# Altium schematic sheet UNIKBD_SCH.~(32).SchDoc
size A4
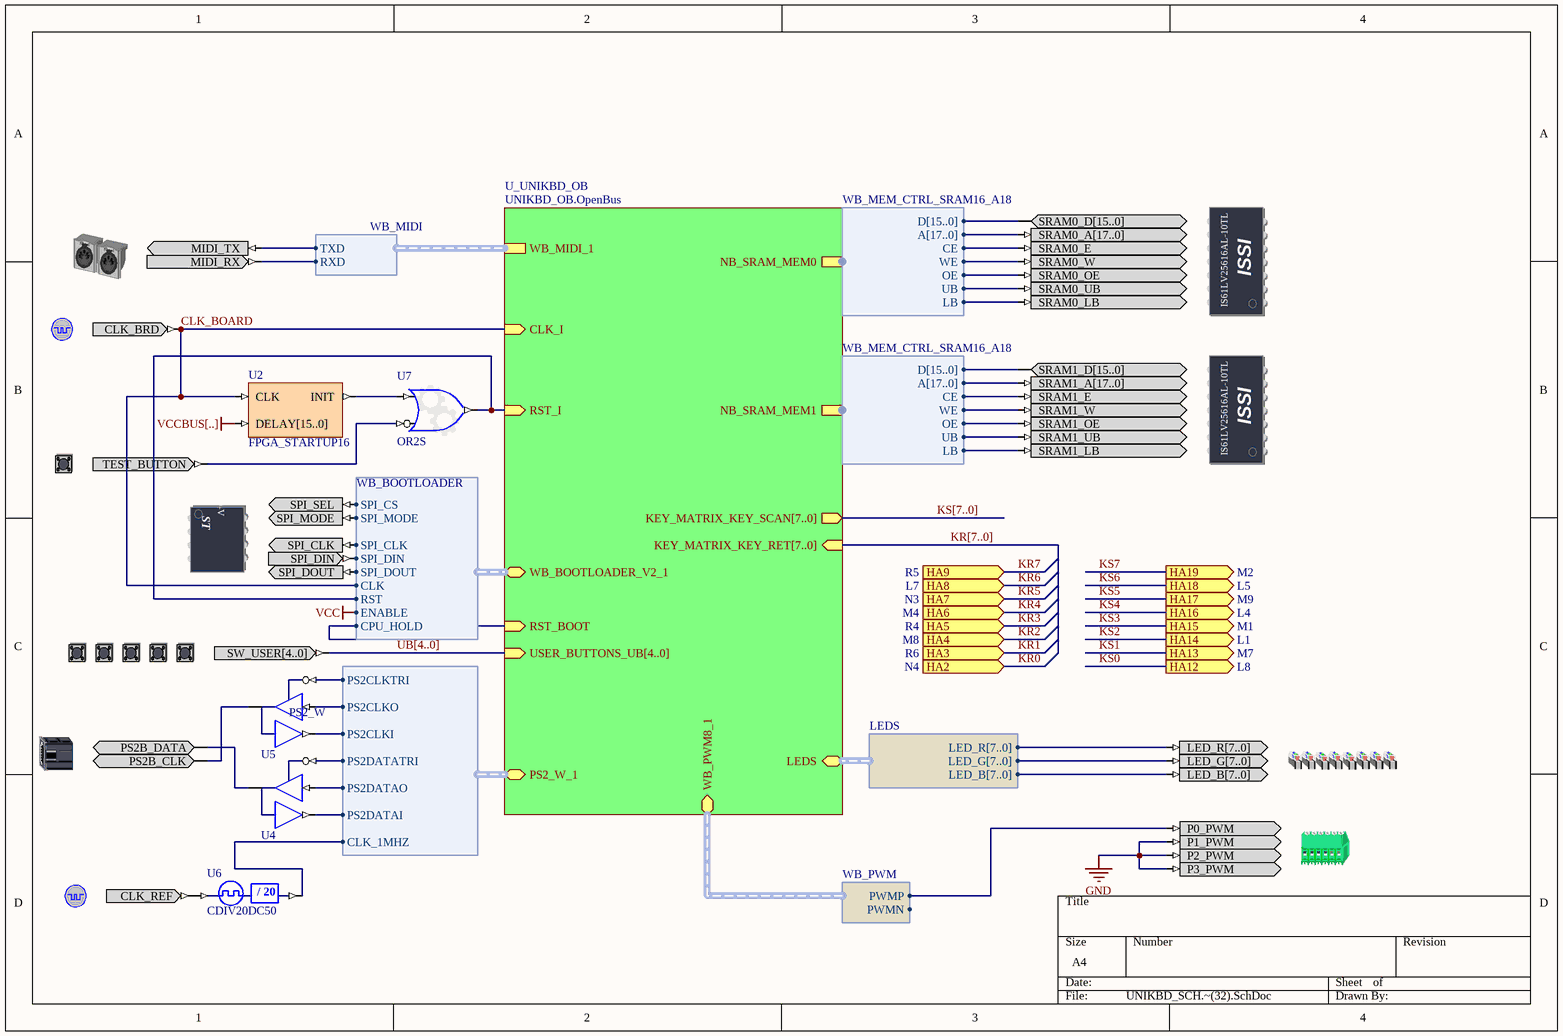
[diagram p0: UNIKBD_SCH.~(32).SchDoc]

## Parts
(Parts that share a designator on the sheet are numbered #1, #2 ... from top to bottom, then left to right.)
?#1  SRAM0  (value not drawn)
?#2  MIDI  (value not drawn)
?#3  CLOCK_BOARD  (value not drawn)
?#4  SRAM1  (value not drawn)
?#5  TEST_BUTTON  (value not drawn)
?#6  SERIALFMEMORY  (value not drawn)
?#7  USER_BUTTONS  (value not drawn)
?#8  LEDS_RGB  (value not drawn)
?#9  PS2B  (value not drawn)
?#10  PWM  (value not drawn)
?#11  CLOCK_REFERENCE  (value not drawn)
U2  FPGA_STARTUP16
U4  IOBUF  (value not drawn)
U5  IOBUF  (value not drawn)
U6  CDIV20DC50
U7  OR2S

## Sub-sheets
U_UNIKBD_OB = UNIKBD_OB.OpenBus: KEY_MATRIX_KEY_SCAN[7..0] (out), KEY_MATRIX_KEY_RET[7..0] (in), WB_MIDI_1 (harness WB_MIDI), NB_SRAM_MEM0 (harness WB_MEM_CTRL_SRAM16_A18), NB_SRAM_MEM1 (harness WB_MEM_CTRL_SRAM16_A18), RST_I (in), CLK_I (in), USER_BUTTONS_UB[4..0] (in), PS2_W_1 (harness PS2_W), LEDS (harness LEDS), WB_PWM8_1 (harness WB_PWM), WB_BOOTLOADER_V2_1 (harness WB_BOOTLOADER), RST_BOOT (in)

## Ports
HA2 (in, see N4), HA3 (in, see R6), HA4 (in, see M8), HA5 (in, see R4), HA6 (in, see M4), HA7 (in, see N3), HA8 (in, see L7), HA9 (in, see R5), HA12 (out, see L8), HA13 (out, see M7), HA14 (out, see L1), HA15 (out, see M1), HA16 (out, see L4), HA17 (out, see M9), HA18 (out, see L5), HA19 (out, see M2)

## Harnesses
WB_MEM_CTRL_SRAM16_A18: D[15..0], A[17..0], CE, WE, OE, UB, LB
WB_MIDI: RXD, TXD
LEDS: LED_R[7..0], LED_G[7..0], LED_B[7..0]
PS2_W: PS2CLKTRI, PS2CLKO, PS2CLKI, PS2DATATRI, PS2DATAO, PS2DATAI, CLK_1MHZ
WB_PWM: PWMN, PWMP
WB_BOOTLOADER: SPI_DOUT, SPI_DIN, SPI_CLK, SPI_MODE, SPI_CS, CLK, RST, ENABLE, CPU_HOLD

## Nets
GND: ?#10.P1_PWM ?#10.P2_PWM ?#10.P3_PWM
VCCBUS[..]: U2.DELAY[15..0]
CLK_BOARD: ?#3.CLK_BRD U2.CLK ; sheet U_UNIKBD_OB/CLK_I, sheet U_UNIKBD_OB/WB_BOOTLOADER_V2_1.CLK
Net?#1_SRAM0_E: ?#1.SRAM0_E ; sheet U_UNIKBD_OB/NB_SRAM_MEM0.CE
Net?#1_SRAM0_LB: ?#1.SRAM0_LB ; sheet U_UNIKBD_OB/NB_SRAM_MEM0.LB
Net?#1_SRAM0_OE: ?#1.SRAM0_OE ; sheet U_UNIKBD_OB/NB_SRAM_MEM0.OE
Net?#1_SRAM0_UB: ?#1.SRAM0_UB ; sheet U_UNIKBD_OB/NB_SRAM_MEM0.UB
Net?#1_SRAM0_W: ?#1.SRAM0_W ; sheet U_UNIKBD_OB/NB_SRAM_MEM0.WE
Net?#2_MIDI_RX: ?#2.MIDI_RX ; sheet U_UNIKBD_OB/WB_MIDI_1.RXD
Net?#2_MIDI_TX: ?#2.MIDI_TX ; sheet U_UNIKBD_OB/WB_MIDI_1.TXD
Net?#4_SRAM1_E: ?#4.SRAM1_E ; sheet U_UNIKBD_OB/NB_SRAM_MEM1.CE
Net?#4_SRAM1_LB: ?#4.SRAM1_LB ; sheet U_UNIKBD_OB/NB_SRAM_MEM1.LB
Net?#4_SRAM1_OE: ?#4.SRAM1_OE ; sheet U_UNIKBD_OB/NB_SRAM_MEM1.OE
Net?#4_SRAM1_UB: ?#4.SRAM1_UB ; sheet U_UNIKBD_OB/NB_SRAM_MEM1.UB
Net?#4_SRAM1_W: ?#4.SRAM1_W ; sheet U_UNIKBD_OB/NB_SRAM_MEM1.WE
Net?#5_TEST_BUTTON: ?#5.TEST_BUTTON U7.I1
Net?#6_SPI_CLK: ?#6.SPI_CLK ; sheet U_UNIKBD_OB/WB_BOOTLOADER_V2_1.SPI_CLK
Net?#6_SPI_DIN: ?#6.SPI_DIN ; sheet U_UNIKBD_OB/WB_BOOTLOADER_V2_1.SPI_DIN
Net?#6_SPI_DOUT: ?#6.SPI_DOUT ; sheet U_UNIKBD_OB/WB_BOOTLOADER_V2_1.SPI_DOUT
Net?#6_SPI_MODE: ?#6.SPI_MODE ; sheet U_UNIKBD_OB/WB_BOOTLOADER_V2_1.SPI_MODE
Net?#6_SPI_SEL: ?#6.SPI_SEL ; sheet U_UNIKBD_OB/WB_BOOTLOADER_V2_1.SPI_CS
Net?#9_PS2B_CLK: ?#9.PS2B_CLK U5.IO
Net?#9_PS2B_DATA: ?#9.PS2B_DATA U4.IO
Net?#10_P0_PWM: ?#10.P0_PWM ; sheet U_UNIKBD_OB/WB_PWM8_1.PWMP
Net?#11_CLK_REF: ?#11.CLK_REF U6.CLKIN
NetU2_INIT: U2.INIT U7.I0
NetU4_I: U4.I ; sheet U_UNIKBD_OB/PS2_W_1.PS2DATAO
NetU4_O: U4.O ; sheet U_UNIKBD_OB/PS2_W_1.PS2DATAI
NetU4_T: U4.T ; sheet U_UNIKBD_OB/PS2_W_1.PS2DATATRI
NetU5_I: U5.I ; sheet U_UNIKBD_OB/PS2_W_1.PS2CLKO
NetU5_O: U5.O ; sheet U_UNIKBD_OB/PS2_W_1.PS2CLKI
NetU5_T: U5.T ; sheet U_UNIKBD_OB/PS2_W_1.PS2CLKTRI
NetU6_CLKDV: U6.CLKDV ; sheet U_UNIKBD_OB/PS2_W_1.CLK_1MHZ
NetU7_O: U7.O ; sheet U_UNIKBD_OB/RST_I, sheet U_UNIKBD_OB/WB_BOOTLOADER_V2_1.RST
(unnamed): sheet U_UNIKBD_OB/RST_BOOT, sheet U_UNIKBD_OB/WB_BOOTLOADER_V2_1.CPU_HOLD

Not connected (* = marked no-connect by the designer): ?#1 SRAM0_A[17..0] SRAM0_D[15..0]; ?#4 SRAM1_A[17..0] SRAM1_D[15..0]; ?#7 SW_USER[4..0]; ?#8 LED_B[7..0] LED_G[7..0] LED_R[7..0]

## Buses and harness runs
bus KR[7..0] = sheet U_UNIKBD_OB/KEY_MATRIX_KEY_RET[7..0]
bus KS[7..0] = sheet U_UNIKBD_OB/KEY_MATRIX_KEY_SCAN[7..0]
bus UB[4..0] = sheet U_UNIKBD_OB/USER_BUTTONS_UB[4..0]

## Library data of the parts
?#1 = SRAM0: Free Static RAM - Daughterboard; PortComponent: True
?#2 = MIDI: MIDI Connector; PortComponent: True
?#3 = CLOCK_BOARD: Global System Clock Supply; PortComponent: True
?#4 = SRAM1: Free Static RAM - Daughterboard; PortComponent: True
?#5 = TEST_BUTTON: Test / Reset Button; PortComponent: True
?#6 = SERIALFMEMORY: Serial SPI Flash RAM; PortComponent: True
?#7 = USER_BUTTONS: Generic User Buttons; PortComponent: True
?#8 = LEDS_RGB: LEDS RGB; PortComponent: True
?#9 = PS2B: Key Board PS2 Connector; PortComponent: True
?#10 = PWM: Pulse Width Modulation; PortComponent: True
?#11 = CLOCK_REFERENCE: Global System Clock Reference Supply; PortComponent: True
U2 = FPGA_STARTUP16: FPGA Startup With 16 Bit Delay
U4 U5 = IOBUF: Input/Output Buffer; Enable: Low; Control: Common Control T; ArchiveName: GENERIC; VHDLIB_SIM: GENERIC_LIB
U6 = CDIV20DC50: Clock Divider by 20 with 50% Duty Cycle Output; DivisorRate: 20; DutyCycle: 50; ArchiveName: GENERIC; VHDLIB_SIM: GENERIC_LIB
U7 = GATE: Configurable Generic Gate; ConfiguratorName: GENERIC_GATE; ConfigurationParameters: {}Version[1.0]{}GateKind[OR]{}BusInput[False]{}GateInputType[Bit]{}GateOutputOption[Normal]{}BusWidth[8]{}RegisterOutputs[False]{}NegativeClockEdge[False]{}InputCount[2]{}InputInvert0[False]{}InputInvert1[True]{}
